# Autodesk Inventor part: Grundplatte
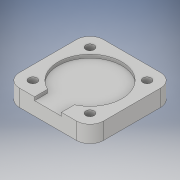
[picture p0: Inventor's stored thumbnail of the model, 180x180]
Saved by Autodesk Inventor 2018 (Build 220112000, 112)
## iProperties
Created: 2018-09
Part Number: Grundplatte
Material: Generisch
Document SubType Name: Modeling
Designer: mathes
Density: 1 g/cm^3
Appearance: Vorgabe
Author: mathes
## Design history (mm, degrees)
sketch "Skizze1"
  geometry: L1 (-12.5, 12.5)-(12.5, 12.5); L2 (12.5, 12.5)-(12.5, -12.5); L3 (12.5, -12.5)-(-12.5, -12.5); L4 (-12.5, -12.5)-(-12.5, 12.5); 1 further point
  constraints: 8 end point, 2 parallel, 1 horizontal, 1 perpendicular
  dimensions: "d0" = 25 distance of L2.end L3.end; "d1" = 25 distance of L1.end L2.end; "d2" = 12.5 distance from line of point (0, 0) L3; "d3" = 12.5 distance from line of point (0, 0) L4
extrude "Extrusion1" new body sketch "Skizze1" distance "d4" = 5; taper "d5" = 0 deg
sketch "Skizze2"
  geometry: C1 r 9.5 at (0, 0); 1 further point
  constraints: 1 centre point, 1 coincident
  dimensions: "d6" = 19 diameter of C1
extrude "Extrusion2" cut sketch "Skizze2" distance "d7" = 1; taper "d8" = 0 deg
sketch "Skizze3"
  geometry: L1 (-12.5, -12.5)-(12.5, -12.5) reference; L2 (-4, -12.5)-(4, -12.5); L3 (4, -12.5)-(4, 0); L4 (4, 0)-(-4, 0); L5 (-4, 0)-(-4, -12.5); 1 further point
  constraints: 8 end point, 2 parallel, 1 horizontal, 1 perpendicular, 1 point on line
  dimensions: "d9" = 4 distance from line of point (0, 0) L3; "d10" = 8 distance between parallel lines of L3 L5
extrude "Extrusion3" cut sketch "Skizze3" distance "d11" = 1; taper "d12" = 0 deg
sketch "Skizze4"
  geometry: 5 further points
  dimensions: "d13" = 8.5 horizontal distance of point (0, 0) point (8.5, 8.5); "d14" = 8.5 horizontal distance of point (0, 0) point (8.5, 8.5); "d15" = 8.5 horizontal distance of point (0, 0) point (-8.5, 8.5); "d16" = 8.5 horizontal distance of point (0, 0) point (-8.5, 8.5); "d17" = 8.5 horizontal distance of point (0, 0) point (-8.5, -8.5); "d18" = 8.5 horizontal distance of point (0, 0) point (-8.5, -8.5); "d19" = 8.5 horizontal distance of point (0, 0) point (8.5, -8.5); "d20" = 8.5 horizontal distance of point (0, 0) point (8.5, -8.5)
hole "Bohrung1" sketch "Skizze4" at (-8.5, 8.5), (8.5, 8.5), (8.5, -8.5), (-8.5, -8.5) diameter "d21" = 2.5; stored, may be unused: countersink angle "d25" = 90 deg, drill point angle "d27" = 118 deg; dims "d22" = 6, "d23" = 4, "d24" = 2, "d26" = 3
fillet "Rundung1" dims "d28" = 4
node "Volumenkörper1"
